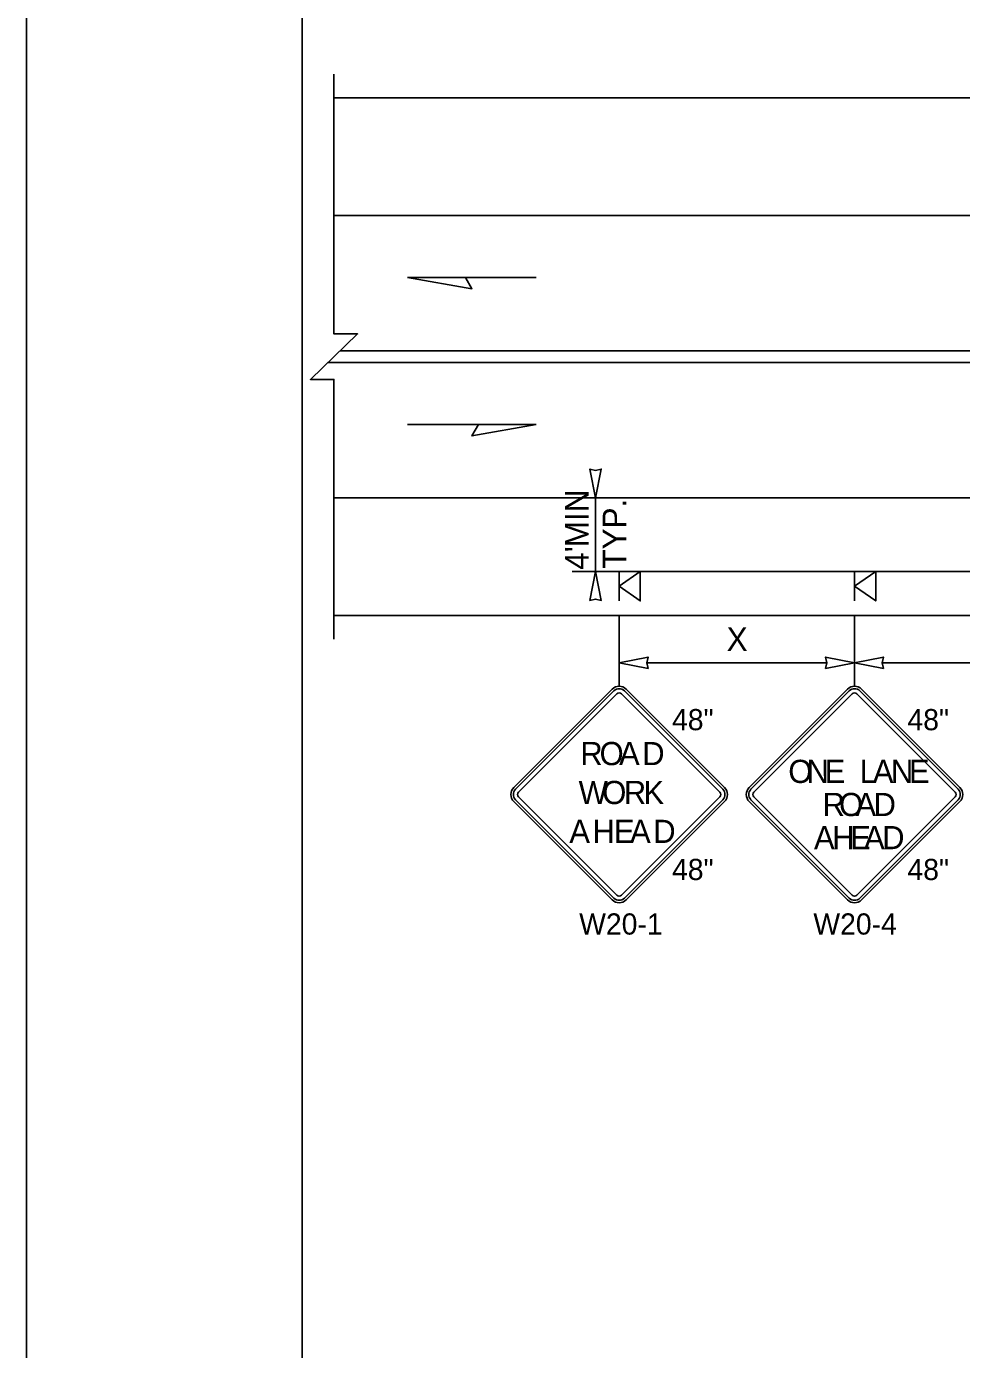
# Model space of a CAD drawing. Extents: x 99999.1 to 100095.7, y 99995 to 100010.7.
# Drawn here: x 99999.062 to 100002.24, y 100003.239 to 100007.734 of the extents above; entities that cross this region are included whole.
import ezdxf

# ---------------------------------------------------------------- set-up
doc = ezdxf.new("R2010")
doc.units = 0
for name, color, linetype in [('RD_ED_ShoulderPavedEdge', 7, 'Continuous'), ('RD_MK_LineDblYellowCenter', 7, 'Continuous'), ('RD_MK_LineEdgeWhite', 7, 'Continuous'), ('SH_GI_PlotLimits', 7, 'Continuous'), ('SH_GI_SheetBorder', 7, 'Continuous'), ('TR_SN_ConstructionSigns', 7, 'Continuous'), ('TR_WZ_PortableSignMountBlk-Org', 7, 'Continuous'), ('TR_WZ_WorkZoneDetails', 7, 'Continuous'), ('TR_WZ_WorkZoneTextCurrent', 7, 'Continuous')]:
    doc.layers.add(name, color=color, linetype=linetype)

msp = doc.modelspace()

# ---------------------------------------------------------------- linework, layer by layer
at = {"layer": 'RD_ED_ShoulderPavedEdge'}
for p, q in [((100000.1076, 100007.4923), (100015.6424, 100007.4923)), ((100000.1076, 100005.7323), (100015.6424, 100005.7323))]:
    msp.add_line(p, q, dxfattribs=at)
at = {"layer": 'RD_MK_LineDblYellowCenter'}
for p, q in [((100000.1282, 100006.6323), (100003.4767, 100006.6323)), ((100000.0869, 100006.5923), (100003.4767, 100006.5923))]:
    msp.add_line(p, q, dxfattribs=at)
at = {"layer": 'RD_MK_LineEdgeWhite'}
for p, q in [((100000.1076, 100007.0923), (100015.6424, 100007.0923)), ((100000.1076, 100006.1323), (100015.6424, 100006.1323))]:
    msp.add_line(p, q, dxfattribs=at)
at = {"layer": 'SH_GI_PlotLimits'}
msp.add_lwpolyline([(99999.0625, 99999.6875), (100016.0625, 99999.6875), (100016.0625, 100010.6875), (99999.0625, 100010.6875)], close=True, dxfattribs=at)
at = {"layer": 'SH_GI_SheetBorder'}
msp.add_line((100000, 100010.375), (100000, 100000), dxfattribs=at)
at = {"layer": 'TR_SN_ConstructionSigns'}
for p, q in [((100001.0528, 100005.4824), (100000.7187, 100005.1483)), ((100001.4346, 100005.1483), (100001.1005, 100005.4824)), ((100001.8528, 100005.4824), (100001.5187, 100005.1483)), ((100002.2346, 100005.1483), (100001.9005, 100005.4824)), ((100001.0588, 100005.4765), (100000.7246, 100005.1424)), ((100000.7346, 100005.1324), (100001.0687, 100005.4665)), ((100001.0846, 100005.4665), (100001.4187, 100005.1324)), ((100001.4287, 100005.1424), (100001.0945, 100005.4765)), ((100001.8588, 100005.4765), (100001.5246, 100005.1424)), ((100001.5346, 100005.1324), (100001.8687, 100005.4665)), ((100001.8846, 100005.4665), (100002.2187, 100005.1324)), ((100002.2287, 100005.1424), (100001.8945, 100005.4765)), ((100000.7187, 100005.1006), (100001.0528, 100004.7665)), ((100000.7246, 100005.1066), (100001.0588, 100004.7725)), ((100001.0687, 100004.7824), (100000.7346, 100005.1165)), ((100001.4187, 100005.1165), (100001.0846, 100004.7824)), ((100001.0945, 100004.7725), (100001.4287, 100005.1066)), ((100001.1005, 100004.7665), (100001.4346, 100005.1006)), ((100001.5187, 100005.1006), (100001.8528, 100004.7665)), ((100001.5246, 100005.1066), (100001.8588, 100004.7725)), ((100001.8687, 100004.7824), (100001.5346, 100005.1165)), ((100002.2187, 100005.1165), (100001.8846, 100004.7824)), ((100001.8945, 100004.7725), (100002.2287, 100005.1066)), ((100001.9005, 100004.7665), (100002.2346, 100005.1006))]:
    msp.add_line(p, q, dxfattribs=at)
for centre, radius, start, end in [((100001.0767, 100005.4586), 0.0338, 45, 135), ((100001.0767, 100005.4586), 0.0253, 45, 135), ((100001.8767, 100005.4586), 0.0338, 45, 135), ((100001.8767, 100005.4586), 0.0253, 45, 135), ((100001.0767, 100005.4586), 0.0113, 45, 135), ((100001.8767, 100005.4586), 0.0113, 45, 135), ((100000.7425, 100005.1245), 0.0338, 135, 225), ((100000.7425, 100005.1245), 0.0253, 135, 225), ((100000.7425, 100005.1245), 0.0113, 135, 225), ((100001.4108, 100005.1245), 0.0113, 315, 45), ((100001.4108, 100005.1245), 0.0253, 315, 45), ((100001.4108, 100005.1245), 0.0338, 315, 45), ((100001.5425, 100005.1245), 0.0338, 135, 225), ((100001.5425, 100005.1245), 0.0253, 135, 225), ((100001.5425, 100005.1245), 0.0113, 135, 225), ((100002.2108, 100005.1245), 0.0113, 315, 45), ((100002.2108, 100005.1245), 0.0253, 315, 45), ((100002.2108, 100005.1245), 0.0338, 315, 45), ((100001.0767, 100004.7904), 0.0338, 225, 315), ((100001.0767, 100004.7904), 0.0253, 225, 315), ((100001.0767, 100004.7904), 0.0113, 225, 315), ((100001.8767, 100004.7904), 0.0338, 225, 315), ((100001.8767, 100004.7904), 0.0253, 225, 315), ((100001.8767, 100004.7904), 0.0113, 225, 315)]:
    msp.add_arc(centre, radius, start, end, dxfattribs=at)
at = {"layer": 'TR_WZ_PortableSignMountBlk-Org'}
for p, q in [((100001.0767, 100005.7824), (100001.0767, 100005.8824)), ((100001.8767, 100005.7824), (100001.8767, 100005.8824))]:
    msp.add_line(p, q, dxfattribs=at)
for points in [[(100001.0767, 100005.8323), (100001.1485, 100005.8824), (100001.1485, 100005.7824)], [(100001.8767, 100005.8323), (100001.9485, 100005.8824), (100001.9485, 100005.7824)]]:
    msp.add_lwpolyline(points, close=True, dxfattribs=at)
at = {"layer": 'TR_WZ_WorkZoneDetails'}
for p, q in [((100000.5541, 100006.8816), (100000.7952, 100006.8816)), ((100000.5987, 100006.3816), (100000.3576, 100006.3816)), ((100000.9167, 100006.1323), (100001.0767, 100006.1323)), ((100000.9967, 100005.8824), (100000.9967, 100006.1323)), ((100000.9167, 100005.8824), (100001.0767, 100005.8824)), ((100001.0767, 100005.8824), (100003.4767, 100005.8824)), ((100001.0767, 100005.7326), (100001.0767, 100005.4923)), ((100001.8767, 100005.7323), (100001.8767, 100005.4923)), ((100001.7829, 100005.5723), (100001.1704, 100005.5723)), ((100002.5829, 100005.5723), (100001.9704, 100005.5723))]:
    msp.add_line(p, q, dxfattribs=at)
msp.add_lwpolyline([(100000.1076, 100005.6523), (100000.1076, 100006.5349), (100000.0275, 100006.5349), (100000.1876, 100006.6898), (100000.1076, 100006.6898), (100000.1076, 100007.5723)], dxfattribs=at)
for points in [[(100000.3576, 100006.8816), (100000.5764, 100006.843), (100000.5541, 100006.8816)], [(100000.7952, 100006.3816), (100000.5764, 100006.343), (100000.5987, 100006.3816)], [(100000.9967, 100006.1323), (100000.9774, 100006.2306), (100000.9967, 100006.2261), (100001.0159, 100006.2306)], [(100000.9967, 100005.8824), (100000.9774, 100005.7841), (100000.9967, 100005.7887), (100001.0159, 100005.7841)], [(100001.0767, 100005.5723), (100001.1749, 100005.5916), (100001.1704, 100005.5723), (100001.1749, 100005.5531)], [(100001.8767, 100005.5723), (100001.7784, 100005.5916), (100001.7829, 100005.5723), (100001.7784, 100005.5531)], [(100001.8767, 100005.5723), (100001.9749, 100005.5916), (100001.9704, 100005.5723), (100001.9749, 100005.5531)]]:
    msp.add_lwpolyline(points, close=True, dxfattribs=at)

# ---------------------------------------------------------------- texts
at = {"layer": 'TR_SN_ConstructionSigns'}
for s, p in [('48"', (100001.2564, 100005.343)), ('48"', (100002.0564, 100005.343)), ('48"', (100001.2564, 100004.8339)), ('48"', (100002.0564, 100004.8339)), ('W20-1', (100000.9408, 100004.6486)), ('W20-4', (100001.7367, 100004.6486))]:
    msp.add_text(s, height=0.072, rotation=360, dxfattribs=at).set_placement(p)
for s, height, p in [('R', 0.0788, (100000.9447, 100005.2243)), ('O', 0.0788, (100001.0101, 100005.2243)), ('A', 0.0788, (100001.0763, 100005.2243)), ('D', 0.0788, (100001.155, 100005.2243)), ('O', 0.0787, (100001.6514, 100005.1638)), ('N', 0.0787, (100001.7136, 100005.1638)), ('E', 0.0787, (100001.7751, 100005.1638)), ('L', 0.0787, (100001.894, 100005.1638)), ('A', 0.0787, (100001.9389, 100005.1638)), ('N', 0.0787, (100002.0003, 100005.1638)), ('E', 0.0787, (100002.0617, 100005.1638)), ('W', 0.0788, (100000.9388, 100005.0921)), ('O', 0.0788, (100001.0192, 100005.0921)), ('R', 0.0788, (100001.0924, 100005.0921)), ('K', 0.0788, (100001.1593, 100005.0921)), ('R', 0.0787, (100001.768, 100005.0513)), ('O', 0.0787, (100001.8239, 100005.0513)), ('A', 0.0787, (100001.8798, 100005.0513)), ('D', 0.0787, (100001.9412, 100005.0513)), ('A', 0.0788, (100000.9073, 100004.9599)), ('H', 0.0788, (100000.9861, 100004.9599)), ('E', 0.0788, (100001.0585, 100004.9599)), ('A', 0.0788, (100001.1137, 100004.9599)), ('D', 0.0788, (100001.1924, 100004.9599)), ('A', 0.0787, (100001.7388, 100004.9388)), ('H', 0.0787, (100001.8003, 100004.9388)), ('E', 0.0787, (100001.8617, 100004.9388)), ('A', 0.0787, (100001.9089, 100004.9388)), ('D', 0.0787, (100001.9704, 100004.9388))]:
    msp.add_text(s, height=height, dxfattribs=at).set_placement(p)
at = {"layer": 'TR_WZ_WorkZoneTextCurrent'}
for s, rotation, p in [('MIN', 90, (100000.9727, 100005.9648)), ('TYP.', 90, (100001.1007, 100005.892)), ("4'", 90, (100000.9727, 100005.8883)), ('X', 360, (100001.4419, 100005.6123))]:
    msp.add_text(s, height=0.08, rotation=rotation, dxfattribs=at).set_placement(p)

doc.saveas('drawing.dxf')
